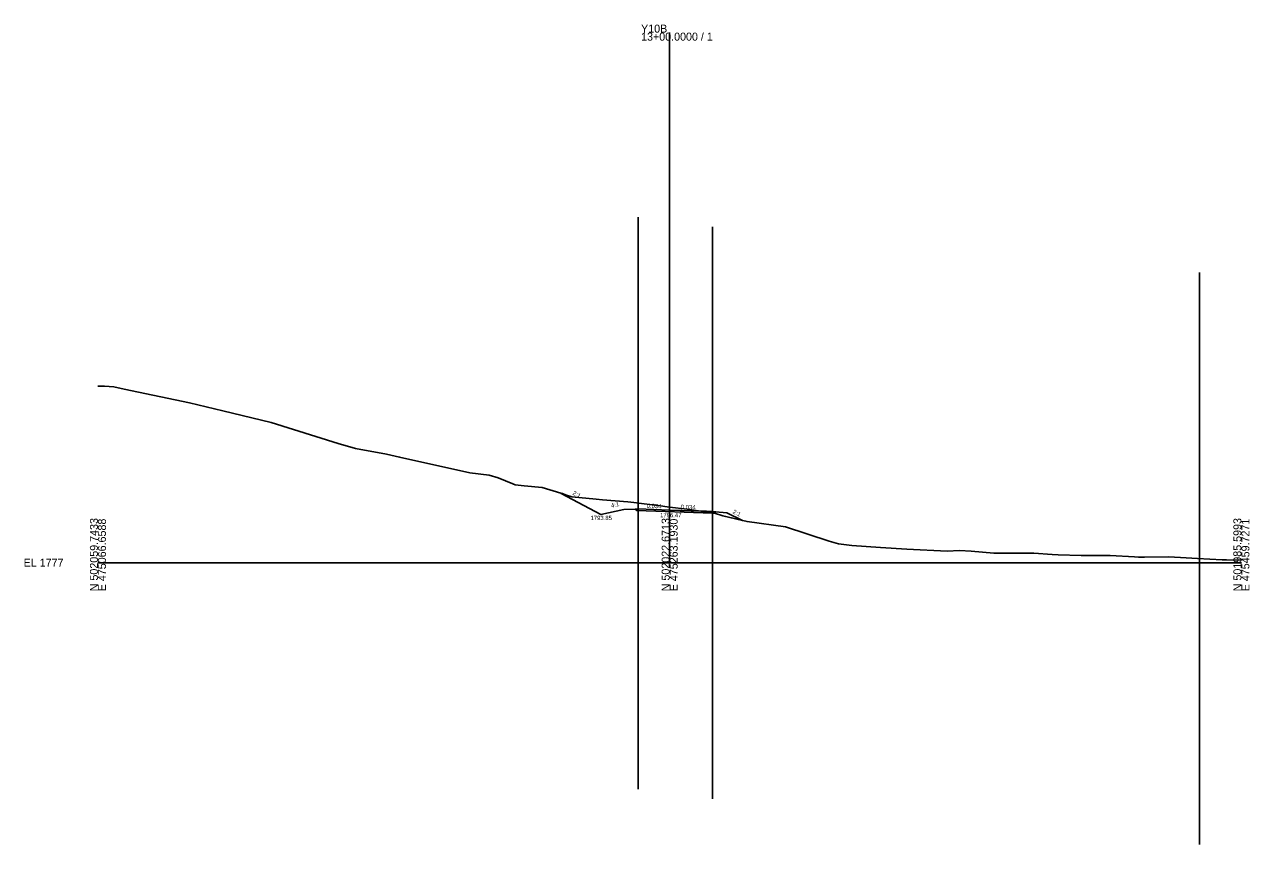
# Model space of a CAD drawing. Extents: x -26 to 1803, y -10 to 9558.
# Drawn here: x -25.7 to 402.8, y 2901.5 to 3188.2 of the extents above; entities that cross this region are included whole.
import ezdxf

# ---------------------------------------------------------------- set-up
doc = ezdxf.new("R2010")
doc.units = 0
for name, color, linetype in [('Exist Cross Section Cell', 7, 'Continuous'), ('Exist XS Center Line Elevation Label', 7, 'Continuous'), ('Exist XS Ground Line', 7, 'Continuous'), ('Prop XS Ditch Slope Text', 7, 'Continuous'), ('Prop XS Ditch Standard Text', 7, 'Continuous'), ('Prop XS Dump Level', 7, 'Continuous'), ('Prop XS Earthwork Shape', 7, 'Continuous'), ('Prop XS EOT Tick Mark', 7, 'Continuous'), ('Prop XS Finish Grade', 7, 'Continuous'), ('Prop XS Finish Grade Earthwork', 7, 'Continuous'), ('Prop XS Finish Grade Pavement', 7, 'Continuous'), ('Prop XS Hydro Typical Ditch Data', 7, 'Continuous'), ('Prop XS Pvmt Edge Slope', 7, 'Continuous'), ('Prop XS SE Text', 7, 'Continuous'), ('Prop XS Shoulder Borrow Shape', 7, 'Continuous'), ('Prop XS Side Slope Text', 7, 'Continuous'), ('Prop XS Subgrade Earthwork', 7, 'Continuous'), ('Scratch_Level_2', 7, 'Continuous')]:
    doc.layers.add(name, color=color, linetype=linetype)

msp = doc.modelspace()

# ---------------------------------------------------------------- linework, layer by layer
at = {"layer": 'Exist Cross Section Cell'}
for p, q in [((200, 3000), (200, 3185.33)), ((0, 3000), (200, 3000)), ((200, 3000), (400, 3000))]:
    msp.add_line(p, q, dxfattribs=at)
at = {"layer": 'Exist XS Ground Line'}
msp.add_lwpolyline([(0, 3061.78), (2.27, 3061.74), (5.58, 3061.45), (9.21, 3060.68), (32, 3055.92), (43.74, 3053.04), (60.6, 3048.97), (84.04, 3041.7), (90.13, 3039.9), (100.9, 3037.89), (105.5, 3036.92), (130.12, 3031.47), (136.91, 3030.55), (139.95, 3029.68), (145.15, 3027.62), (146.01, 3027.17), (149.14, 3026.88), (155.35, 3026.35), (161.97, 3024.26), (162.49, 3024.14), (163.56, 3023.71), (165.75, 3022.99), (174.24, 3022.18), (176.56, 3021.98), (185.34, 3021.24), (187.41, 3020.99), (190.11, 3020.67), (193.94, 3020.23), (195.97, 3020), (200, 3019.47), (206.15, 3018.67), (215.64, 3017.35), (218.56, 3016.44), (227.06, 3014.35), (240.49, 3012.52), (255.82, 3007.52), (259.04, 3006.65), (263.68, 3006.07), (273.73, 3005.28), (283.01, 3004.74), (297.06, 3004.03), (301.35, 3004.28), (305.51, 3004.08), (313.4, 3003.3), (318.05, 3003.34), (323.58, 3003.29), (327.35, 3003.28), (333.75, 3002.81), (335.91, 3002.77), (343.93, 3002.57), (347.34, 3002.57), (354.11, 3002.57), (362.61, 3002.04), (363.96, 3001.99), (366.11, 3001.97), (374.47, 3002.1), (378.72, 3001.87), (384.65, 3001.51), (393.32, 3001.06), (394.82, 3000.99), (400, 3000.83)], dxfattribs=at)
at = {"layer": 'Prop XS Dump Level'}
for p, q in [((189.01, 3018.78), (200, 3018.41)), ((200, 3018.41), (212.84, 3017.97))]:
    msp.add_line(p, q, dxfattribs=at)
at = {"layer": 'Prop XS Earthwork Shape'}
for points in [[(188.46, 3018.26), (187.98, 3018.76), (184, 3018.65), (175.95, 3016.85), (162.08, 3024.23), (162.49, 3024.14), (163.56, 3023.71), (165.75, 3022.99), (174.24, 3022.18), (176.56, 3021.98), (185.34, 3021.24), (187.41, 3020.99), (190.11, 3020.67), (193.94, 3020.23), (195.97, 3020), (200, 3019.47), (206.15, 3018.67), (215.58, 3017.36), (215.56, 3017.34), (215, 3017.36)], [(215.58, 3017.36), (215.64, 3017.35), (218.56, 3016.44), (225.52, 3014.73), (220.01, 3017.48), (216.04, 3017.81)]]:
    msp.add_lwpolyline(points, close=True, dxfattribs=at)
at = {"layer": 'Prop XS EOT Tick Mark'}
for p, q in [((189.01, 3018.78), (189.03, 3019.78)), ((215, 3017.9), (215, 3018.9))]:
    msp.add_line(p, q, dxfattribs=at)
at = {"layer": 'Prop XS Finish Grade'}
for p, q in [((189.01, 3018.78), (187.98, 3018.76)), ((215, 3017.9), (216.04, 3017.81))]:
    msp.add_line(p, q, dxfattribs=at)
at = {"layer": 'Prop XS Finish Grade Earthwork'}
for p, q in [((175.95, 3016.85), (162.08, 3024.23)), ((184, 3018.65), (175.95, 3016.85)), ((187.98, 3018.76), (184, 3018.65)), ((216.04, 3017.81), (220.01, 3017.48)), ((220.01, 3017.48), (225.52, 3014.73))]:
    msp.add_line(p, q, dxfattribs=at)
at = {"layer": 'Prop XS Finish Grade Pavement'}
for p, q in [((189.01, 3018.78), (200, 3018.41)), ((200, 3018.41), (215, 3017.9))]:
    msp.add_line(p, q, dxfattribs=at)
at = {"layer": 'Prop XS Hydro Typical Ditch Data'}
msp.add_line((184, 3018.65), (175.95, 3016.85), dxfattribs=at)
at = {"layer": 'Prop XS Pvmt Edge Slope'}
for p, q in [((189.01, 3018.78), (188.46, 3018.26)), ((215, 3017.9), (215.56, 3017.34))]:
    msp.add_line(p, q, dxfattribs=at)
at = {"layer": 'Prop XS Shoulder Borrow Shape'}
for points in [[(189.01, 3018.78), (188.46, 3018.26), (187.98, 3018.76)], [(215, 3017.9), (215.56, 3017.34), (216.04, 3017.81)]]:
    msp.add_lwpolyline(points, close=True, dxfattribs=at)
at = {"layer": 'Prop XS Subgrade Earthwork'}
for p, q in [((188.46, 3018.26), (187.98, 3018.76)), ((215, 3017.36), (188.46, 3018.26)), ((215, 3017.36), (215.56, 3017.34)), ((215.56, 3017.34), (216.04, 3017.81))]:
    msp.add_line(p, q, dxfattribs=at)
at = {"layer": 'Scratch_Level_2'}
for p, q in [((189, 3120.8), (189, 2920.8)), ((215, 3117.44), (215, 2917.44)), ((385.33, 3101.48), (385.33, 2901.48))]:
    msp.add_line(p, q, dxfattribs=at)

# ---------------------------------------------------------------- texts
at = {"layer": 'Exist Cross Section Cell'}
for s, p in [('Y10B', (190, 3185.33)), ('13+00.0000 / 1', (190, 3182.53)), ('EL 1777', (-26, 2998.6))]:
    msp.add_text(s, height=2.8, dxfattribs=at).set_placement(p)
for s, p in [('N 502059.7433', (0, 2990)), ('E 475066.6588', (2.8, 2990)), ('N 502022.6713', (200, 2990)), ('E 475263.1930', (202.8, 2990)), ('N 501985.5993', (400, 2990)), ('E 475459.7271', (402.8, 2990))]:
    msp.add_text(s, height=2.8, rotation=90, dxfattribs=at).set_placement(p)
at = {"layer": 'Exist XS Center Line Elevation Label'}
msp.add_text('1796.47', height=1.5, dxfattribs=at).set_placement((196.66, 3015.9))
at = {"layer": 'Prop XS Ditch Slope Text'}
msp.add_text('4:1', height=1.5, rotation=12.6046, dxfattribs=at).set_placement((179.65, 3019.22))
at = {"layer": 'Prop XS Ditch Standard Text'}
msp.add_text('1793.85', height=1.5, rotation=359.7711, dxfattribs=at).set_placement((172.31, 3014.92))
at = {"layer": 'Prop XS Dump Level'}
for rotation, p in [(358.5683, (184, 3018.61)), (359.7711, (220.01, 3017.44))]:
    msp.add_text('Case1', height=0.04, rotation=rotation, dxfattribs=at).set_placement(p)
at = {"layer": 'Prop XS SE Text'}
for p in [(191.94, 3019.18), (203.84, 3018.78)]:
    msp.add_text('0.034', height=1.5, rotation=358.0527, dxfattribs=at).set_placement(p)
at = {"layer": 'Prop XS Side Slope Text'}
for rotation, p in [(332.0033, (165.88, 3023.91)), (333.4349, (221.9, 3017.35))]:
    msp.add_text('2:1', height=1.5, rotation=rotation, dxfattribs=at).set_placement(p)

doc.saveas('drawing.dxf')
